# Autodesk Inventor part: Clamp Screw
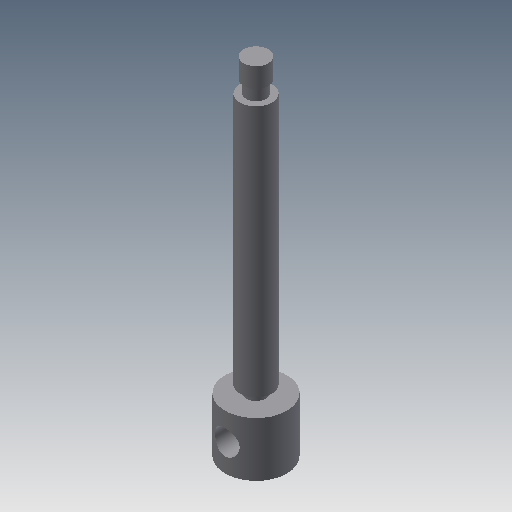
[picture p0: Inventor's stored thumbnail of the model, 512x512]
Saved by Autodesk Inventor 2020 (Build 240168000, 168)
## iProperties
Created: 2002-02
Part Number: Clamp Screw
Document SubType Name: Modeling
Designer: ***
Density: 1 g/cm^3
Material: Generic
Appearance: Default
Control State: 0
Master: False
Checked Out: False
Shininess: 77.0
Length Units: 11269
Angle Units: 11279
Time Units: 11290
Mass Units: 11283
Length Display Precision: 3
Angle Display Precision: 2
Density: 0.0
Volumn: 0.0
Area: 0.0
PropertySet Name: Model Information
Author: ***
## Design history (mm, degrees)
sketch "Sketch1"
  geometry: L1 (0, 140)-(5, 140); L2 (5, 140)-(5, 132); L3 (5, 132)-(4, 132); L4 (4, 132)-(4, 127); L5 (4, 127)-(6.5, 127); L6 (6.5, 127)-(6.5, 25); L7 (6.5, 25)-(4, 25); L8 (4, 25)-(4, 22); L9 (4, 22)-(12.5, 22); L10 (12.5, 22)-(12.5, 0); L11 (12.5, 0)-(0, 0); L12 (0, 0)-(0, 140)
  constraints: 24 end point, 10 parallel, 1 horizontal, 1 perpendicular
  dimensions: "d0" = 10 diameter of L2 L12; "d1" = 8 diameter of L4 L12; "d2" = 13 diameter of L6 L12; "d3" = 8 diameter of L7.end L12; "d4" = 25 diameter of L10 L12; "d5" = 3 distance from line of L7.end L9; "d6" = 8 distance of L1.end L2.end; "d7" = 13 vertical distance of L1.end L5.end; "d8" = 22 distance of L9.end L10.end; "d10" = 102 distance of L5.end L6.end
revolve "Revolution1" sketch "Sketch1" stored, may be unused: angle "d11" = 90 deg
sketch "Sketch3"
  geometry: L1 (-12.5, 0)-(12.5, 0) reference; C1 r 5 at (-0.113, 11)
  constraints: 1 centre point
  dimensions: "d13" = 10 diameter of C1; "d14" = 11 distance from line of L1 C1.centre
extrude "Extrusion1" cut sketch "Sketch3" extent not by distance; stored distance "d15" = 10; taper "d16" = 0 deg
body "Solid1"
